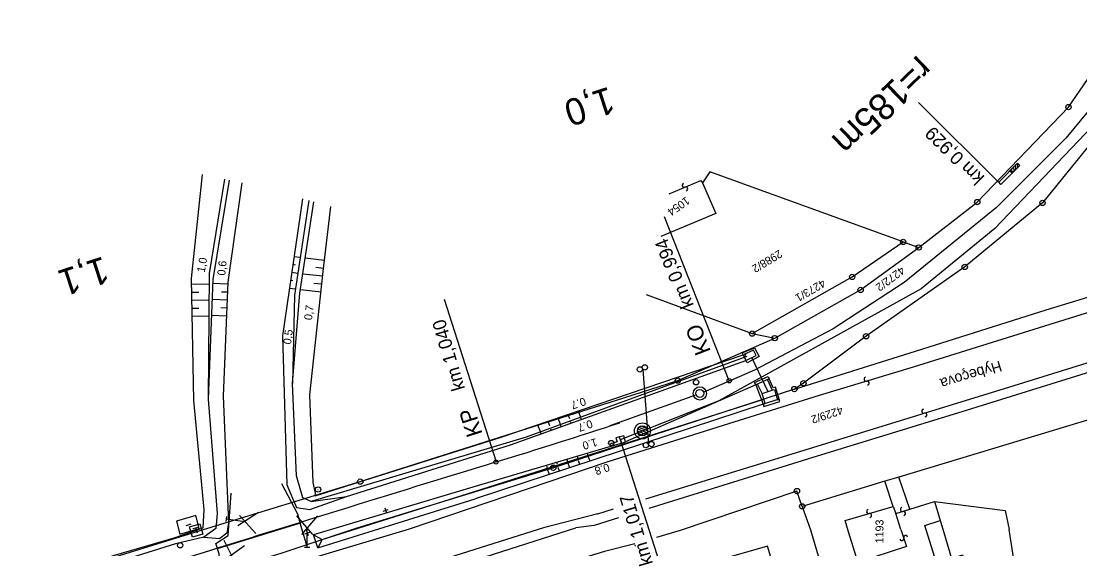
# Model space of a CAD drawing. Extents: x -658910 to -658078, y -1170373 to -1169331.
# Drawn here: x -658648.2 to -658449.7, y -1170003.8 to -1169904.9 of the extents above; entities that cross this region are included whole.
import ezdxf

# ---------------------------------------------------------------- set-up
doc = ezdxf.new("R2010")
doc.units = 0
for name, color, linetype in [('Vrstva 1', 7, 'Continuous'), ('Vrstva 10', 7, 'Continuous'), ('Vrstva 11', 7, 'Continuous'), ('Vrstva 12', 7, 'Continuous'), ('Vrstva 13', 7, 'Continuous'), ('Vrstva 14', 7, 'Continuous'), ('Vrstva 22', 7, 'Continuous'), ('Vrstva 23', 7, 'Continuous'), ('Vrstva 26', 7, 'Continuous'), ('Vrstva 27', 7, 'Continuous'), ('Vrstva 30', 7, 'Continuous'), ('Vrstva 34', 7, 'Continuous'), ('Vrstva 38', 7, 'Continuous'), ('Vrstva 39', 7, 'Continuous'), ('Vrstva 6', 7, 'Continuous'), ('Vrstva 7', 7, 'Continuous'), ('Vrstva 8', 7, 'Continuous'), ('Vrstva 9', 7, 'Continuous')]:
    doc.layers.add(name, color=color, linetype=linetype)

msp = doc.modelspace()

# ---------------------------------------------------------------- linework, layer by layer
at = {"layer": 'Vrstva 1'}
for p, q in [((-658451.909, -1169920.99), (-658451.809, -1169920.99)), ((-658469.011, -1169938.809), (-658468.911, -1169938.809)), ((-658456.788, -1169938.969), (-658456.688, -1169938.969)), ((-658479.999, -1169947.32), (-658479.899, -1169947.32)), ((-658471.37, -1169950.961), (-658471.27, -1169950.961)), ((-658490.89, -1169955.289), (-658490.79, -1169955.289)), ((-658489.859, -1169963.961), (-658489.759, -1169963.961)), ((-658506.999, -1169964.32), (-658506.899, -1169964.32)), ((-658525.159, -1169972.281), (-658525.059, -1169972.281)), ((-658503.312, -1169973.871), (-658503.212, -1169973.871)), ((-658501.609, -1169972.781), (-658501.509, -1169972.781)), ((-658548.499, -1169988.611), (-658548.399, -1169988.611)), ((-658584.706, -1169991.227), (-658584.606, -1169991.227)), ((-658592.61, -1169992.7), (-658592.51, -1169992.7)), ((-658613.207, -1169999.979), (-658613.207, -1169999.979))]:
    msp.add_line(p, q, dxfattribs=at)
for points in [[(-658535.25, -1169975.531), (-658525.109, -1169972.281), (-658506.949, -1169964.32), (-658490.84, -1169955.289), (-658479.949, -1169947.32), (-658468.961, -1169938.809), (-658451.859, -1169920.99), (-658433.102, -1169893.621), (-658430.531, -1169888.559), (-658387.09, -1169803.74)], [(-658428.09, -1169905.961), (-658431.891, -1169908.08), (-658444.09, -1169923.359), (-658456.738, -1169938.969), (-658471.32, -1169950.961), (-658489.809, -1169963.961), (-658501.559, -1169972.781), (-658503.262, -1169973.871), (-658537.41, -1169985.039)], [(-658613.207, -1169999.979), (-658584.656, -1169991.227), (-658535.25, -1169975.531)], [(-658537.41, -1169985.039), (-658548.449, -1169988.611), (-658585.293, -1169999.957)], [(-658750.043, -1170042.514), (-658671.512, -1170017.973), (-658613.207, -1169999.979)], [(-658585.293, -1169999.957), (-658599.563, -1170004.705), (-658613.664, -1170008.939), (-658714.84, -1170040.211), (-658749.914, -1170050.912)]]:
    msp.add_lwpolyline(points, dxfattribs=at)
for centre in [(-658451.859, -1169920.99), (-658468.961, -1169938.809), (-658456.738, -1169938.969), (-658479.949, -1169947.32), (-658471.32, -1169950.961), (-658490.84, -1169955.289), (-658506.949, -1169964.32), (-658489.809, -1169963.961), (-658525.109, -1169972.281), (-658503.262, -1169973.871), (-658501.559, -1169972.781), (-658548.449, -1169988.611), (-658584.656, -1169991.227), (-658592.56, -1169992.7)]:
    msp.add_circle(centre, 0.499, dxfattribs=at)
at = {"layer": 'Vrstva 10'}
for p, q in [((-658549.501, -1169979.9), (-658549.192, -1169980.675)), ((-658547.607, -1169979.256), (-658547.092, -1169980.549)), ((-658545.713, -1169978.612), (-658545.404, -1169979.388)), ((-658543.82, -1169977.969), (-658543.339, -1169979.177)), ((-658543.194, -1169979.572), (-658543.356, -1169979.183)), ((-658551.394, -1169980.543), (-658550.845, -1169981.921)), ((-658548.841, -1169981.6), (-658548.933, -1169981.379)), ((-658546.959, -1169980.924), (-658547.112, -1169980.556)), ((-658545.077, -1169980.248), (-658545.169, -1169980.027)), ((-658550.724, -1169982.276), (-658550.868, -1169981.929)), ((-658547.83, -1169987.611), (-658547.749, -1169987.901)), ((-658546.318, -1169987.72), (-658546.318, -1169987.72)), ((-658545.912, -1169987.045), (-658545.776, -1169987.529)), ((-658545.371, -1169988.626), (-658545.791, -1169987.534)), ((-658543.994, -1169986.479), (-658543.912, -1169986.769)), ((-658543.471, -1169988), (-658543.723, -1169987.345)), ((-658542.076, -1169985.912), (-658541.963, -1169986.312)), ((-658541.572, -1169987.375), (-658541.978, -1169986.317)), ((-658549.749, -1169988.177), (-658549.589, -1169988.746)), ((-658549.17, -1169989.877), (-658549.604, -1169988.751)), ((-658547.271, -1169989.251), (-658547.523, -1169988.596))]:
    msp.add_line(p, q, dxfattribs=at)
for points in [[(-658412.34, -1169868.25), (-658427.96, -1169897.31), (-658435.92, -1169909.92), (-658444.78, -1169921.89), (-658465.67, -1169943.73), (-658479.49, -1169955.1), (-658517.4, -1169976.07), (-658535.91, -1169983.41)], [(-658858.81, -1170075.77), (-658835.33, -1170068.814), (-658806.5, -1170059.46), (-658781.728, -1170051.951), (-658759.08, -1170044.56), (-658716.43, -1170031.76), (-658690.72, -1170023.742), (-658663.72, -1170015.47), (-658630.927, -1170005.047), (-658619.527, -1170001.735), (-658614.09, -1169999.864), (-658613.911, -1169996.427), (-658615.839, -1169976.036), (-658616.28, -1169953.162), (-658614.25, -1169933.651)], [(-658610.105, -1169934.508), (-658612.959, -1169952.166), (-658613.171, -1169975.75), (-658611.485, -1169997.195), (-658611.739, -1169999.997), (-658613.983, -1170001.632), (-658619.297, -1170002.886), (-658632.661, -1170007.108), (-658660.45, -1170015.82), (-658687.716, -1170024.188), (-658719.16, -1170034.07), (-658752.32, -1170044.29), (-658781.421, -1170053.208), (-658807.34, -1170061.38), (-658834.998, -1170069.996)], [(-658609.258, -1169934.684), (-658612.28, -1169953.321), (-658613.171, -1169975.75)], [(-658606.83, -1169935.186), (-658609.466, -1169953.802), (-658610.356, -1169975.207), (-658609.375, -1169998.935), (-658609.654, -1170000.858), (-658610.974, -1170001.898)], [(-658595.508, -1169938.185), (-658599.245, -1169963.902), (-658598.442, -1169991.808), (-658596.63, -1169996.047), (-658594.077, -1169996.431), (-658587.23, -1169994.03)], [(-658594.315, -1169938.505), (-658596.96, -1169956.27), (-658597.366, -1169972.85)], [(-658593.83, -1169994.94), (-658595.432, -1169994.26), (-658596.599, -1169990.15), (-658597.366, -1169972.85), (-658595.975, -1169955.885), (-658593.358, -1169938.763)], [(-658591.591, -1169951.797), (-658590.164, -1169939.621)], [(-658597.078, -1169948.99), (-658595.901, -1169949.161)], [(-658591.351, -1169949.745), (-658594.976, -1169949.344)], [(-658597.51, -1169951.959), (-658596.343, -1169952.128)], [(-658597.294, -1169950.475), (-658596.825, -1169950.543)], [(-658593.1, -1169993.87), (-658593.038, -1169993.379), (-658593.449, -1169991.364), (-658594.076, -1169974.977), (-658591.591, -1169951.797)], [(-658591.525, -1169951.235), (-658592.951, -1169951.078)], [(-658609.483, -1169954.215), (-658612.31, -1169954.097)], [(-658597.725, -1169953.443), (-658597.261, -1169953.511)], [(-658591.691, -1169952.726), (-658595.429, -1169952.313)], [(-658591.851, -1169954.218), (-658593.33, -1169954.054)], [(-658616.26, -1169954.215), (-658612.977, -1169954.151)], [(-658616.231, -1169955.714), (-658614.935, -1169955.689)], [(-658609.545, -1169955.713), (-658610.675, -1169955.667)], [(-658597.941, -1169954.928), (-658596.785, -1169955.096)], [(-658592.01, -1169955.709), (-658595.883, -1169955.28)], [(-658616.202, -1169957.214), (-658613.004, -1169957.152)], [(-658609.608, -1169957.212), (-658612.43, -1169957.095)], [(-658616.173, -1169958.714), (-658614.911, -1169958.689)], [(-658609.67, -1169958.711), (-658610.798, -1169958.664)], [(-658616.144, -1169960.213), (-658613.031, -1169960.153)], [(-658609.732, -1169960.209), (-658612.549, -1169960.092)], [(-658512.19, -1169967.79), (-658553.55, -1169982.91), (-658593.83, -1169994.94)], [(-658593.1, -1169993.87), (-658558.21, -1169982.86), (-658512.852, -1169967.442)], [(-658512.852, -1169967.442), (-658512.346, -1169968.492)], [(-658512.303, -1169967.109), (-658512.649, -1169967.881), (-658512.336, -1169968.481)], [(-658508.19, -1169974.36), (-658511.23, -1169967.92)], [(-658593.83, -1169994.94), (-658587.23, -1169994.03), (-658556.47, -1169984.34), (-658512.346, -1169968.492)], [(-658510.51, -1169973.09), (-658534.91, -1169983.74)], [(-658563.42, -1169993.16), (-658508.96, -1169975.78)], [(-658509.27, -1169974.68), (-658507.41, -1169974.05)], [(-658509.09, -1169976.68), (-658563.09, -1169994.46)], [(-658534.91, -1169983.74), (-658535.26, -1169982.62), (-658536.703, -1169983.014), (-658536.473, -1169983.748), (-658537.86, -1169984.19), (-658537.73, -1169984.63), (-658534.91, -1169983.74)], [(-658537.73, -1169984.63), (-658563.55, -1169992.25), (-658593.42, -1170001.18), (-658591.8, -1170002.09), (-658592.6, -1170003.65), (-658593.42, -1170001.18)], [(-658591.8, -1170002.09), (-658563.42, -1169993.16)], [(-658592.6, -1170003.65), (-658563.09, -1169994.46)], [(-658613.983, -1170001.632), (-658610.974, -1170001.898)]]:
    msp.add_lwpolyline(points, dxfattribs=at)
for points in [[(-658513.014, -1169967.086), (-658510.736, -1169966.123), (-658509.851, -1169967.791), (-658512.13, -1169968.94), (-658512.346, -1169968.492), (-658510.4, -1169967.57), (-658510.9, -1169966.586), (-658512.852, -1169967.442)], [(-658510.73, -1169972.66), (-658508.2, -1169971.5), (-658507.96, -1169971.96), (-658510.51, -1169973.09)], [(-658506.42, -1169975.86), (-658506.11, -1169975.78), (-658506.78, -1169973.53), (-658507.21, -1169973.62), (-658507.96, -1169971.96), (-658508.289, -1169972.106), (-658507.41, -1169974.05), (-658506.98, -1169973.94)], [(-658510.51, -1169973.09), (-658509.09, -1169976.68), (-658508.72, -1169976.57), (-658508.96, -1169975.78), (-658509.27, -1169974.68), (-658510.16, -1169972.935)], [(-658509.09, -1169976.68), (-658508.96, -1169977.111), (-658505.983, -1169976.212), (-658506.11, -1169975.78)]]:
    msp.add_lwpolyline(points, close=True, dxfattribs=at)
at = {"layer": 'Vrstva 12'}
for p, q in [((-658580.384, -1169996.739), (-658579.431, -1169996.438)), ((-658580.058, -1169996.112), (-658579.757, -1169997.065)), ((-658595.04, -1170001.021), (-658594.087, -1170000.72)), ((-658594.714, -1170000.394), (-658594.413, -1170001.347))]:
    msp.add_line(p, q, dxfattribs=at)
at = {"layer": 'Vrstva 13'}
for points in [[(-658599.394, -1169991.562), (-658596.426, -1169997.244), (-658595.649, -1169999.996), (-658594.6, -1170003.49)], [(-658611.169, -1170007.954), (-658611.101, -1170004.744), (-658611.699, -1170002.836), (-658609.401, -1170001.323), (-658608.825, -1169993.398)]]:
    msp.add_lwpolyline(points, dxfattribs=at)
at = {"layer": 'Vrstva 14'}
msp.add_line((-658611.4, -1170003.79), (-658596.06, -1169998.99), dxfattribs=at)
for centre in [(-658521.69, -1169972.587), (-658618.41, -1170003.17)]:
    msp.add_circle(centre, 0.5, dxfattribs=at)
at = {"layer": 'Vrstva 22'}
for p, q in [((-658531.108, -1169982.406), (-658532.692, -1169981.743)), ((-658530.882, -1169982.095), (-658532.625, -1169981.363)), ((-658530.799, -1169981.723), (-658532.419, -1169981.043)), ((-658530.912, -1169981.268), (-658532.017, -1169980.806)), ((-658536.194, -1169982.716), (-658535.626, -1169984.104)), ((-658533.133, -1169982.274), (-658535.91, -1169983.41)), ((-658531.538, -1169982.632), (-658532.55, -1169982.208)), ((-658537.64, -1169983.99), (-658537.54, -1169983.99))]:
    msp.add_line(p, q, dxfattribs=at)
for centre, radius in [((-658531.745, -1169981.706), 1.5), ((-658531.747, -1169981.711), 0.949), ((-658531.747, -1169981.712), 0.948), ((-658537.59, -1169983.99), 0.5)]:
    msp.add_circle(centre, radius, dxfattribs=at)
at = {"layer": 'Vrstva 23'}
msp.add_line((-658535.91, -1169983.41), (-658528.549, -1170006.455), dxfattribs=at)
at = {"layer": 'Vrstva 26'}
for p, q in [((-658462.077, -1169933.001), (-658462.084, -1169932.153)), ((-658461.705, -1169932.623), (-658461.712, -1169931.775)), ((-658461.333, -1169932.245), (-658461.338, -1169931.593)), ((-658462.84, -1169932.921), (-658462.84, -1169932.921)), ((-658462.84, -1169932.921), (-658462.412, -1169933.342)), ((-658462.828, -1169932.933), (-658462.828, -1169932.909)), ((-658462.449, -1169933.305), (-658462.455, -1169932.531))]:
    msp.add_line(p, q, dxfattribs=at)
for points in [[(-658464.944, -1169935.06), (-658461.437, -1169931.496), (-658461.009, -1169931.916), (-658464.516, -1169935.48), (-658464.944, -1169935.06)], [(-658531.64, -1169970.19), (-658530.59, -1169984.27)]]:
    msp.add_lwpolyline(points, dxfattribs=at)
msp.add_lwpolyline([(-658461.009, -1169931.916), (-658462.412, -1169933.342), (-658462.84, -1169932.921), (-658461.437, -1169931.496)], close=True, dxfattribs=at)
for centre in [(-658532.235, -1169970.171), (-658531.295, -1169969.798), (-658530.065, -1169984.178), (-658531.114, -1169984.382)]:
    msp.add_circle(centre, 0.5, dxfattribs=at)
at = {"layer": 'Vrstva 27'}
msp.add_line((-658464.516, -1169935.48), (-658479.973, -1169920.155), dxfattribs=at)
at = {"layer": 'Vrstva 30'}
for p, q in [((-658609.704, -1169997.734), (-658609.836, -1169998.726)), ((-658603.708, -1169997.017), (-658607.572, -1169999.53)), ((-658607.309, -1169997.548), (-658604.234, -1170000.982)), ((-658596.6, -1169997.64), (-658593.6, -1170001.14)), ((-658595.6, -1170001.14), (-658592.6, -1169997.64)), ((-658609.77, -1169998.23), (-658606.3, -1169998.69)), ((-658594.6, -1170003.49), (-658594.6, -1169999.99)), ((-658610.209, -1170002.229), (-658608.149, -1170006.353)), ((-658610.089, -1170005.867), (-658606.329, -1170003.201)), ((-658595.1, -1170003.49), (-658594.1, -1170003.49))]:
    msp.add_line(p, q, dxfattribs=at)
at = {"layer": 'Vrstva 34'}
for p, q in [((-658616.021, -1170000.031), (-658615.061, -1169999.749)), ((-658615.541, -1169999.89), (-658615.259, -1170000.85))]:
    msp.add_line(p, q, dxfattribs=at)
msp.add_lwpolyline([(-658616.642, -1169999.693), (-658614.723, -1169999.128), (-658614.158, -1170001.047), (-658616.077, -1170001.612), (-658616.642, -1169999.693)], dxfattribs=at)
at = {"layer": 'Vrstva 38'}
for points in [[(-658527.671, -1169941.521), (-658515.528, -1169972.246)], [(-658568.917, -1169957.028), (-658559.19, -1169987.54)]]:
    msp.add_lwpolyline(points, dxfattribs=at)
for centre in [(-658515.458, -1169972.312), (-658559.2, -1169987.545)]:
    msp.add_circle(centre, 0.4, dxfattribs=at)
at = {"layer": 'Vrstva 6'}
msp.add_line((-658616.425, -1169999.19), (-658617.379, -1169999.491), dxfattribs=at)
for points in [[(-658443.997, -1169916.707), (-658452.354, -1169926.822), (-658465.375, -1169939.824), (-658482.656, -1169953.863), (-658495.968, -1169962.556), (-658510.71, -1169970.323), (-658520.257, -1169974.434)], [(-658521.619, -1169974.97), (-658537.844, -1169980.783)], [(-658614.88, -1170000), (-658615.5, -1169997.55), (-658619.13, -1169998.61), (-658618.49, -1170001.05), (-658614.88, -1170000)]]:
    msp.add_lwpolyline(points, dxfattribs=at)
for radius in [1.246, 0.752]:
    msp.add_circle((-658520.985, -1169974.684), radius, dxfattribs=at)
for centre, radius, start, end in [((-658948.541, -1168718.871), 1327.07, 287.061119, 288.112797), ((-655551.219, -1179788.762), 10252.407, 107.0611194, 107.4078056)]:
    msp.add_arc(centre, radius, start, end, dxfattribs=at)
at = {"layer": 'Vrstva 8'}
for p, q in [((-658482.902, -1169946.281), (-658482.802, -1169946.281)), ((-658482.902, -1169946.281), (-658482.802, -1169946.281)), ((-658492.472, -1169952.85), (-658492.372, -1169952.85)), ((-658492.422, -1169952.85), (-658492.422, -1169952.85)), ((-658511.222, -1169963.469), (-658511.122, -1169963.469)), ((-658511.222, -1169963.469), (-658511.122, -1169963.469)), ((-658502.82, -1169992.99), (-658502.72, -1169992.99)), ((-658501.839, -1169995.871), (-658501.739, -1169995.871)), ((-658501.839, -1169995.871), (-658501.739, -1169995.871)), ((-658508.301, -1170003.301), (-658508.301, -1170003.301))]:
    msp.add_line(p, q, dxfattribs=at)
for points in [[(-658531.039, -1169956.16), (-658511.172, -1169963.469), (-658492.422, -1169952.85), (-658482.852, -1169946.281), (-658519.102, -1169933.121), (-658520.5, -1169935.191), (-658517.961, -1169940.949), (-658528.309, -1169945.25)], [(-658526.73, -1169937.24), (-658520.809, -1169934.73), (-658520.5, -1169935.191)], [(-658482.852, -1169946.281), (-658479.949, -1169947.32)], [(-658503.262, -1169973.871), (-658479.34, -1169966.379), (-658456.07, -1169959.039), (-658431.148, -1169951.469)], [(-658538.18, -1169987.449), (-658516.57, -1169980.629), (-658498.551, -1169975.039), (-658480.922, -1169969.711), (-658449.5, -1169959.891), (-658431.48, -1169954.41)], [(-658511.172, -1169963.469), (-658506.949, -1169964.32)], [(-658531.1, -1169994.474), (-658495.73, -1169983.559), (-658462.051, -1169973.17), (-658438.48, -1169965.891), (-658437.801, -1169966.629), (-658437.48, -1169967.469)], [(-658432.57, -1169965.9), (-658437.48, -1169967.469), (-658471.859, -1169978.121), (-658499.012, -1169986.42), (-658530.54, -1169996.247)], [(-658433.32, -1169974.6), (-658443.578, -1169978.26), (-658483.641, -1169990.371), (-658486.309, -1169991.16), (-658501.789, -1169995.871), (-658500.211, -1170000.27)], [(-658575.438, -1170000.053), (-658538.18, -1169987.449)], [(-658493.078, -1170000.621), (-658493.73, -1169998.49), (-658484.75, -1169995.91), (-658486.309, -1169991.16)], [(-658484.75, -1169995.91), (-658484.23, -1169997.23), (-658481.59, -1169996.41), (-658483.641, -1169990.371)], [(-658501.789, -1169995.871), (-658502.77, -1169992.99), (-658524.699, -1170000.359)], [(-658481.59, -1169996.41), (-658476.969, -1169994.92), (-658475.41, -1170000.15)], [(-658476.969, -1169994.92), (-658463.75, -1169996.621), (-658462.98, -1170000.219)], [(-658540.129, -1169997.26), (-658550.277, -1169999.916)], [(-658540.129, -1169997.26), (-658537.19, -1169996.353)], [(-658483.281, -1170000.219), (-658484.23, -1169997.23)], [(-658540.789, -1169999.441), (-658544.246, -1169999.895)], [(-658536.237, -1169998.022), (-658540.789, -1169999.441)], [(-658478.551, -1170000.289), (-658478.801, -1169999.449), (-658475.93, -1169998.531)], [(-658750.074, -1170053.912), (-658680.031, -1170031.988), (-658636.086, -1170018.248), (-658589.152, -1170004.176), (-658575.438, -1170000.053)], [(-658550.277, -1169999.916), (-658596.203, -1170014.398), (-658595.582, -1170016.34), (-658544.246, -1169999.895)], [(-658524.699, -1170000.359), (-658529.137, -1170001.696)], [(-658500.211, -1170000.27), (-658498.801, -1170005.15), (-658492.879, -1170007.641)], [(-658483.281, -1170000.219), (-658482.219, -1170003.41), (-658488.371, -1170005.359), (-658488.09, -1170006.15), (-658490.352, -1170006.84), (-658490.68, -1170006.059), (-658491.359, -1170006.24), (-658493.078, -1170000.621)], [(-658472.578, -1170009.809), (-658475.32, -1170010.641), (-658478.551, -1170000.289)], [(-658475.41, -1170000.15), (-658473.809, -1170005.609), (-658471.711, -1170004.941), (-658468.391, -1170014.49), (-658470.539, -1170015.289), (-658472.578, -1170009.809), (-658470.301, -1170009.059)], [(-658459.801, -1170020.74), (-658462.98, -1170000.219)], [(-658533.199, -1170002.92), (-658538.844, -1170004.318), (-658555.117, -1170009.242), (-658558.262, -1170010.266), (-658561.211, -1170011.133), (-658568.297, -1170013.295), (-658574.137, -1170015.18), (-658594.008, -1170021.287), (-658588.469, -1170037.996), (-658584.152, -1170051.688), (-658581.859, -1170059.557), (-658580.82, -1170062.693), (-658575.98, -1170078.678), (-658571.766, -1170092.223)], [(-658533.154, -1170003.074), (-658533.088, -1170003.297)]]:
    msp.add_lwpolyline(points, dxfattribs=at)
msp.add_lwpolyline([(-658519.828, -1170006.65), (-658517.102, -1170015.539), (-658505.73, -1170011.82), (-658508.301, -1170003.301)], close=True, dxfattribs=at)
for centre in [(-658482.852, -1169946.281), (-658482.852, -1169946.281), (-658492.422, -1169952.85), (-658511.172, -1169963.469), (-658511.172, -1169963.469), (-658502.77, -1169992.99), (-658501.789, -1169995.871), (-658501.789, -1169995.871)]:
    msp.add_circle(centre, 0.499, dxfattribs=at)
for centre, radius, start, end in [((-658523.912, -1169935.631), 0.376, 105.96617, 292.2773), ((-658523.623, -1169936.326), 0.377, 285.29013, 112.95334), ((-658489.834, -1169972.017), 0.376, 99.86694, 286.17807), ((-658489.62, -1169972.739), 0.377, 279.19089, 106.85411), ((-658478.997, -1169978.01), 0.376, 100.18081, 286.49195), ((-658478.779, -1169978.73), 0.377, 279.50477, 107.16799), ((-658489.337, -1169996.836), 0.376, 99.05774, 285.36888), ((-658489.134, -1169997.561), 0.377, 278.3817, 106.04491), ((-658483.017, -1169996.459), 0.376, 100.35035, 286.66148), ((-658482.797, -1169997.179), 0.377, 279.67431, 107.33752), ((-658482.392, -1170001.688), 0.377, 10.93669, 198.59991), ((-658483.108, -1170001.924), 0.376, 191.61274, 17.92387)]:
    msp.add_arc(centre, radius, start, end, dxfattribs=at)

# ---------------------------------------------------------------- texts
at = {"layer": 'Vrstva 11'}
for s, rotation, p in [('1,0', 79.98077, (-658613.821, -1169952.091)), ('0,6', 84.07652, (-658609.976, -1169952.644)), ('4272/2', 216.71642, (-658483.244, -1169950.765)), ('0,7', 82.50082, (-658593.715, -1169961.011)), ('0,5', 82.55822, (-658597.628, -1169965.555)), ('0.7', 198.12519, (-658542.639, -1169975.401)), ('0.7', 199.33767, (-658541.402, -1169979.586)), ('1.0', 196.32263, (-658540.459, -1169983.06)), ('0.8', 197.98277, (-658538.2, -1169987.753))]:
    msp.add_text(s, height=1.5, rotation=rotation, dxfattribs=at).set_placement(p)
at = {"layer": 'Vrstva 23'}
msp.add_text('km 1,017', height=2.5, rotation=106.61095, dxfattribs=at).set_placement((-658529.755, -1170006.584))
at = {"layer": 'Vrstva 27'}
msp.add_text('km 0,929', height=2.5, rotation=135.31196, dxfattribs=at).set_placement((-658467.457, -1169934.085))
at = {"layer": 'Vrstva 39'}
for s, height, rotation, p in [('r=185m', 5, 223.8987, (-658480.149, -1169911.04)), ('km 0,994', 2.5, 111.85226, (-658522.067, -1169958.149)), ('km 1,040', 2.5, 106.1542, (-658564.981, -1169973.785)), ('KO', 3, 111.26938, (-658518.873, -1169966.782)), ('KP', 3, 107.74897, (-658561.686, -1169982.259))]:
    msp.add_text(s, height=height, rotation=rotation, dxfattribs=at).set_placement(p)
at = {"layer": 'Vrstva 7'}
for s, p in [('1,0', (-658537.993, -1169917.101)), ('1,1', (-658632.816, -1169948.924))]:
    msp.add_text(s, height=4.999, rotation=197.99256, dxfattribs=at).set_placement(p)
at = {"layer": 'Vrstva 9'}
for s, height, rotation, p in [('1054', 1.5, 215.13209, (-658523.549, -1169937.7)), ('2988/2', 1.5, 210.96103, (-658506.105, -1169947.692)), ('4273/1', 1.5, 210.44916, (-658497.969, -1169953.203)), ('Hybeçova', 2, 196.86416, (-658464.736, -1169968.538)), ('4229/2', 1.5, 198.06436, (-658494.421, -1169977.057)), ('1193', 1.5, 89.7363, (-658486.561, -1170002.805))]:
    msp.add_text(s, height=height, rotation=rotation, dxfattribs=at).set_placement(p)

doc.saveas('drawing.dxf')
